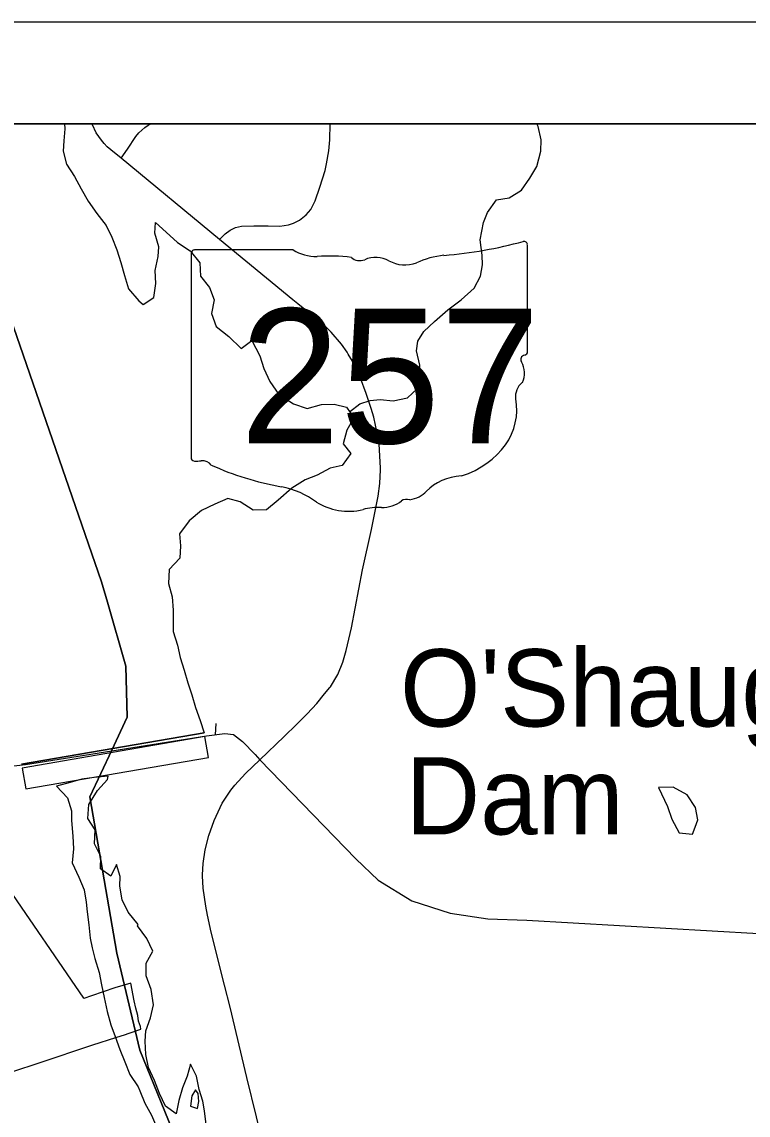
# Model space of a CAD drawing. Extents: x 0 to 34, y 0 to 22.
# Drawn here: x 13.35 to 14.062, y 9.213 to 10.284 of the extents above; entities that cross this region are included whole.
import ezdxf

# ---------------------------------------------------------------- set-up
doc = ezdxf.new("R2010")
doc.units = 0
for name, color, linetype in [('GM_X_Corporation', 7, 'Continuous'), ('GM_X_County_Road', 7, 'Continuous'), ('GM_X_Hydro', 7, 'Continuous'), ('GM_X_Hydro_Text', 7, 'Continuous'), ('GM_X_Major_Lake', 7, 'Continuous'), ('GM_X_Major_River', 7, 'Continuous'), ('GM_X_Minor_Lake', 7, 'Continuous'), ('GM_X_Minor_River', 7, 'Continuous'), ('GM_X_State_Location', 7, 'Continuous'), ('GM_X_State_Route', 7, 'Continuous'), ('GM_X_State_Shield', 7, 'Continuous'), ('GM_X_Township_Road', 7, 'Continuous'), ('SH_Data', 7, 'Continuous')]:
    doc.layers.add(name, color=color, linetype=linetype)

msp = doc.modelspace()

# ---------------------------------------------------------------- linework, layer by layer
at = {"layer": 'GM_X_Corporation'}
for points in [[(19.5646, 10.1841), (12.7646, 10.1841), (12.7646, 8.6719), (12.7953, 8.6676), (12.8119, 8.6756), (12.8296, 8.6783), (12.8448, 8.6761), (12.8988, 8.6726), (13.0467, 8.6615), (13.1161, 8.6564), (13.1948, 8.6507), (13.3525, 8.6386), (13.4613, 8.6292), (13.7169, 8.6042), (13.795, 8.6047), (14.2608, 8.5815), (14.4977, 8.5718), (14.6084, 8.5661), (14.9063, 8.5471), (15.334, 8.5309), (15.3473, 8.5302), (16.0546, 8.4904)], [(13.5392, 9.0957), (13.4655, 9.2762), (13.4429, 9.3712), (13.4167, 9.5246), (13.438, 9.5701), (13.4532, 9.6025), (13.452, 9.6526), (13.4339, 9.7153), (13.4281, 9.7354), (13.3254, 10.0317), (13.2907, 10.1441), (13.2832, 10.1841), (12.7646, 10.1841), (12.7646, 8.6719)], [(17.9872, 10.1841), (13.2832, 10.1841), (13.2907, 10.1441), (13.3254, 10.0317), (13.4281, 9.7354), (13.4339, 9.7153), (13.452, 9.6526), (13.4532, 9.6025), (13.438, 9.5701), (13.4167, 9.5246), (13.4429, 9.3712), (13.4655, 9.2762), (13.5392, 9.0957), (13.554, 9.0226), (13.5893, 8.9175), (13.6099, 8.8643), (13.6779, 8.8077), (13.7002, 8.7685), (13.7209, 8.7116), (13.7246, 8.6669), (13.7169, 8.6042), (13.795, 8.6047), (14.2608, 8.5815)], [(13.3412, 9.2552), (13.3669, 9.2637), (13.4194, 9.2813), (13.4422, 9.2886), (13.4514, 9.2917), (13.454, 9.2926), (13.4664, 9.2968), (13.4662, 9.2993), (13.4644, 9.3045), (13.4635, 9.3102), (13.4617, 9.3173), (13.46, 9.3244), (13.4568, 9.342), (13.4411, 9.3372), (13.4182, 9.3294), (13.4108, 9.3269), (13.4107, 9.327), (13.3332, 9.4401)]]:
    msp.add_lwpolyline(points, dxfattribs=at)
at = {"layer": 'GM_X_County_Road'}
msp.add_lwpolyline([(13.065, 9.5737), (13.1018, 9.5801), (13.1145, 9.5803), (13.1252, 9.5789), (13.1359, 9.5759), (13.213, 9.5505), (13.2403, 9.5469), (13.2511, 9.5459), (13.2722, 9.5464), (13.2818, 9.5474), (13.3193, 9.5524), (13.3535, 9.5562), (13.4382, 9.5696), (13.5308, 9.5842), (13.549, 9.5866), (13.5575, 9.5856), (13.5662, 9.5786), (13.5786, 9.5659), (13.5833, 9.5609)], dxfattribs=at)
at = {"layer": 'GM_X_Hydro'}
for p, q in [((13.5294, 9.5835), (13.3502, 9.5527)), ((13.533, 9.5629), (13.5294, 9.5835)), ((13.3537, 9.5322), (13.533, 9.5629)), ((13.3502, 9.5527), (13.3537, 9.5322))]:
    msp.add_line(p, q, dxfattribs=at)
at = {"layer": 'GM_X_Major_Lake'}
msp.add_line((13.5288, 9.5872), (13.3496, 9.5564), dxfattribs=at)
for points in [[(13.3916, 10.1841), (13.3921, 10.1792), (13.3909, 10.1674), (13.3905, 10.1575), (13.3935, 10.1446), (13.4014, 10.1324), (13.4082, 10.1206), (13.415, 10.1085), (13.4233, 10.0963), (13.4327, 10.0845), (13.438, 10.073), (13.4429, 10.0605), (13.447, 10.0483), (13.4504, 10.0354), (13.4545, 10.0225), (13.4647, 10.0107)], [(13.4647, 10.0107), (13.4687, 10.0072), (13.4794, 10.0139), (13.4811, 10.0275), (13.4806, 10.0405), (13.4834, 10.0541), (13.4843, 10.0636), (13.4804, 10.0769), (13.4809, 10.0875), (13.4914, 10.0779), (13.5026, 10.0678), (13.515, 10.0597), (13.5243, 10.0478), (13.5249, 10.0349), (13.5338, 10.0237), (13.5386, 10.0115), (13.5357, 9.9982), (13.5404, 9.9856), (13.5528, 9.9756), (13.5648, 9.964), (13.5755, 9.9718), (13.5832, 9.9569), (13.5872, 9.9443), (13.5931, 9.9317), (13.602, 9.919), (13.6163, 9.9097), (13.6295, 9.905), (13.6436, 9.9089), (13.6561, 9.9095), (13.6682, 9.9063), (13.6753, 9.8959), (13.6686, 9.8839), (13.665, 9.8706), (13.6725, 9.861), (13.6639, 9.8494), (13.6521, 9.8465), (13.6395, 9.8399), (13.6277, 9.8351), (13.6147, 9.827), (13.6012, 9.8154), (13.5897, 9.8057), (13.5768, 9.8055), (13.564, 9.8137), (13.5519, 9.8169), (13.539, 9.8114), (13.526, 9.8052), (13.5141, 9.7951), (13.5044, 9.7823), (13.5054, 9.7705), (13.5048, 9.7584), (13.4944, 9.7472), (13.4938, 9.7335), (13.4974, 9.7206), (13.4984, 9.7076), (13.4982, 9.6959), (13.4984, 9.6864), (13.5024, 9.673), (13.5052, 9.6612), (13.5092, 9.6486), (13.5128, 9.6364), (13.5165, 9.6246), (13.5201, 9.612), (13.5248, 9.5994), (13.5288, 9.5872)]]:
    msp.add_lwpolyline(points, dxfattribs=at)
at = {"layer": 'GM_X_Major_River'}
msp.add_line((13.3496, 9.5564), (13.5288, 9.5872), dxfattribs=at)
for points in [[(13.3916, 10.1841), (13.3921, 10.1792), (13.3909, 10.1674), (13.3905, 10.1575), (13.3935, 10.1446), (13.4014, 10.1324), (13.4082, 10.1206), (13.415, 10.1085), (13.4233, 10.0963), (13.4327, 10.0845), (13.438, 10.073), (13.4429, 10.0605), (13.447, 10.0483), (13.4504, 10.0354), (13.4545, 10.0225), (13.4647, 10.0107)], [(13.4647, 10.0107), (13.4687, 10.0072), (13.4794, 10.0139), (13.4811, 10.0275), (13.4806, 10.0405), (13.4834, 10.0541), (13.4843, 10.0636), (13.4804, 10.0769), (13.4809, 10.0875), (13.4914, 10.0779), (13.5026, 10.0678), (13.515, 10.0597), (13.5243, 10.0478), (13.5249, 10.0349), (13.5338, 10.0237), (13.5386, 10.0115), (13.5357, 9.9982), (13.5404, 9.9856), (13.5528, 9.9756), (13.5648, 9.964), (13.5755, 9.9718), (13.5832, 9.9569), (13.5872, 9.9443), (13.5931, 9.9317), (13.602, 9.919), (13.6163, 9.9097), (13.6295, 9.905), (13.6436, 9.9089), (13.6561, 9.9095), (13.6682, 9.9063), (13.6753, 9.8959), (13.6686, 9.8839), (13.665, 9.8706), (13.6725, 9.861), (13.6639, 9.8494), (13.6521, 9.8465), (13.6395, 9.8399), (13.6277, 9.8351), (13.6147, 9.827), (13.6012, 9.8154), (13.5897, 9.8057), (13.5768, 9.8055), (13.564, 9.8137), (13.5519, 9.8169), (13.539, 9.8114), (13.526, 9.8052), (13.5141, 9.7951), (13.5044, 9.7823), (13.5054, 9.7705), (13.5048, 9.7584), (13.4944, 9.7472), (13.4938, 9.7335), (13.4974, 9.7206), (13.4984, 9.7076), (13.4982, 9.6959), (13.4984, 9.6864), (13.5024, 9.673), (13.5052, 9.6612), (13.5092, 9.6486), (13.5128, 9.6364), (13.5165, 9.6246), (13.5201, 9.612), (13.5248, 9.5994), (13.5288, 9.5872)], [(13.4346, 9.5447), (13.4209, 9.5436), (13.4088, 9.5417), (13.3973, 9.5384), (13.384, 9.535), (13.3946, 9.5236), (13.3987, 9.5107), (13.3987, 9.5012), (13.3998, 9.486), (13.4005, 9.4735), (13.3993, 9.4598), (13.4057, 9.4457), (13.4109, 9.4335), (13.4128, 9.4214), (13.4139, 9.4119), (13.4154, 9.399), (13.4168, 9.3861), (13.4187, 9.3766), (13.4213, 9.3659), (13.4258, 9.3522), (13.428, 9.3401), (13.4306, 9.3279), (13.4336, 9.3142), (13.437, 9.3009), (13.4415, 9.2895), (13.446, 9.277), (13.4509, 9.2648), (13.4557, 9.2523), (13.464, 9.2401)], [(13.464, 9.3995), (13.4541, 9.4113), (13.4481, 9.4235), (13.4459, 9.4368), (13.4463, 9.4463), (13.4426, 9.4581), (13.4372, 9.4467), (13.427, 9.454), (13.4274, 9.4661), (13.421, 9.4783), (13.4218, 9.492), (13.4147, 9.5034), (13.4155, 9.517), (13.4239, 9.5307), (13.4338, 9.5416), (13.4346, 9.5447)], [(13.5306, 9.2033), (13.5289, 9.2167), (13.5275, 9.2262), (13.5239, 9.2376), (13.5211, 9.2506), (13.5152, 9.2624), (13.512, 9.2507), (13.5073, 9.2394), (13.5037, 9.2269), (13.5012, 9.2137), (13.4907, 9.2214), (13.4848, 9.2337), (13.4801, 9.2466), (13.4742, 9.2593), (13.4713, 9.2718), (13.4708, 9.2851), (13.4713, 9.295), (13.4761, 9.3078), (13.4789, 9.3207), (13.4768, 9.3355), (13.4717, 9.3489), (13.4719, 9.3614), (13.4782, 9.3731), (13.4723, 9.3857), (13.4634, 9.398), (13.464, 9.3995)], [(13.464, 9.2401), (13.4655, 9.2362), (13.4706, 9.2244), (13.4769, 9.2125), (13.4879, 9.1873)], [(13.5201, 9.2373), (13.5166, 9.2313), (13.5153, 9.2214), (13.5221, 9.219)], [(13.5221, 9.219), (13.5234, 9.2259), (13.5227, 9.2338), (13.5201, 9.2373)]]:
    msp.add_lwpolyline(points, dxfattribs=at)
at = {"layer": 'GM_X_Minor_Lake'}
for points in [[(14.0101, 9.4949), (14.0128, 9.5021), (14.0105, 9.5142), (14.0022, 9.5264), (13.9886, 9.5339), (13.9742, 9.5336)], [(13.9742, 9.5336), (13.9829, 9.515), (13.9871, 9.5025), (13.9943, 9.4892), (14.0075, 9.488), (14.0101, 9.4949)]]:
    msp.add_lwpolyline(points, dxfattribs=at)
at = {"layer": 'GM_X_Minor_River'}
for points in [[(13.6712, 9.9018), (13.6814, 9.9097), (13.6913, 9.9131), (13.7011, 9.9139), (13.714, 9.9127), (13.728, 9.9157), (13.7378, 9.9248), (13.7408, 9.9355), (13.7401, 9.9476), (13.737, 9.9616), (13.7382, 9.9711), (13.7442, 9.9806), (13.7544, 9.9905), (13.7677, 10.0019), (13.7805, 10.0117), (13.7934, 10.0231), (13.7995, 10.0349), (13.8017, 10.0459), (13.8013, 10.0553), (13.7994, 10.0705), (13.8025, 10.0876), (13.8066, 10.0974), (13.8153, 10.1096), (13.8278, 10.1115), (13.8399, 10.1191), (13.8479, 10.1308), (13.8547, 10.1422), (13.8588, 10.1574), (13.8592, 10.1684), (13.8562, 10.1817), (13.8547, 10.1841)], [(13.54, 9.5965), (13.5395, 9.5853), (13.5396, 9.585)]]:
    msp.add_lwpolyline(points, dxfattribs=at)
at = {"layer": 'GM_X_State_Route'}
for points in [[(13.6205, 10.0077), (13.6157, 10.0115), (13.5438, 10.0708), (13.4472, 10.1504), (13.437, 10.1587), (13.4337, 10.1616), (13.4307, 10.1648), (13.4279, 10.1681), (13.4229, 10.1754), (13.419, 10.1832), (13.4187, 10.1841)], [(13.644, 9.9891), (13.6342, 9.9966), (13.6205, 10.0077)], [(13.67, 9.9585), (13.6689, 9.9603), (13.6634, 9.9681), (13.6532, 9.9799), (13.6447, 9.9886), (13.644, 9.9891)], [(13.7014, 9.845), (13.7015, 9.847), (13.7003, 9.8701), (13.6967, 9.8889), (13.6951, 9.8966), (13.6925, 9.9053), (13.6876, 9.9197), (13.682, 9.9348), (13.6757, 9.9488), (13.67, 9.9585)], [(13.6525, 9.6324), (13.6597, 9.6445), (13.6645, 9.6565), (13.668, 9.668), (13.6731, 9.6903), (13.6839, 9.7469), (13.6927, 9.7865), (13.6992, 9.8191), (13.7008, 9.8316), (13.7014, 9.845)], [(13.5833, 9.5609), (13.6775, 9.4636), (13.6992, 9.4427), (13.7324, 9.4227), (13.7698, 9.4104), (13.8068, 9.4048), (13.8451, 9.4036), (14.0723, 9.3904), (14.0991, 9.3891), (14.1268, 9.39), (14.1489, 9.3934), (14.1842, 9.4053), (14.2169, 9.4248), (14.2365, 9.4427), (14.2565, 9.4665), (14.2663, 9.484), (14.2791, 9.5138), (14.2854, 9.538), (14.291, 9.5695), (14.3093, 9.6835), (14.3144, 9.7107), (14.3208, 9.7392), (14.3335, 9.7728), (14.3427, 9.7884)], [(13.5833, 9.5609), (13.6071, 9.5837), (13.6191, 9.5953), (13.6295, 9.6057), (13.6392, 9.6159), (13.6468, 9.6253), (13.652, 9.6316), (13.6525, 9.6324)], [(13.5271, 9.4481), (13.5276, 9.4592), (13.5296, 9.4724), (13.5333, 9.4867), (13.5383, 9.5012), (13.5464, 9.5182), (13.5547, 9.5309), (13.5586, 9.5358), (13.5693, 9.5475), (13.5833, 9.5609)], [(13.532, 9.4084), (13.5302, 9.4172), (13.5278, 9.435), (13.5271, 9.4471), (13.5271, 9.4481)], [(13.5485, 9.3399), (13.5354, 9.3918), (13.532, 9.4084)], [(13.7952, 8.6041), (13.7909, 8.6123), (13.7503, 8.704), (13.7279, 8.7713), (13.6989, 8.8523), (13.6706, 8.9337), (13.6563, 8.9771), (13.6306, 9.0465), (13.5895, 9.1723), (13.5705, 9.2494), (13.554, 9.3184), (13.5485, 9.3399)]]:
    msp.add_lwpolyline(points, dxfattribs=at)
at = {"layer": 'GM_X_State_Shield'}
for p, q in [((13.8456, 9.9609), (13.8456, 10.0655)), ((13.516, 10.0571), (13.516, 9.857)), ((13.6158, 10.0606), (13.5192, 10.0606)), ((13.8456, 9.9609), (13.8456, 9.9609))]:
    msp.add_line(p, q, dxfattribs=at)
for centre, major_axis, start_param, end_param in [((13.7282, 10.3334), (0.3495, 0), 4.814394, 5.042369), ((13.8419, 10.066), (0.00367, 0), 6.141152, 7.989035), ((13.5198, 10.0576), (0.00382, 0), 1.712693, 3.28349), ((13.6388, 10.0838), (0.037, 0), 4.042523, 4.731795), ((13.651, 9.9482), (0.133, 0), 1.404758, 1.657858), ((13.6812, 10.0586), (0.0107, 0), 3.836095, 5.185415), ((13.6969, 10.0355), (0.0222, 0), 0.950623, 2.079405), ((13.7728, 9.9995), (0.0703, 0), 1.699011, 2.107814), ((13.7256, 10.0672), (0.0267, 0), 4.081561, 5.145723), ((13.8447, 9.9532), (0.00568, 0), 1.883978, 3.671073), ((13.8417, 9.9605), (0.00393, 0), 5.05454, 6.418171), ((13.8086, 9.9399), (0.0341, 0), 5.934695, 6.695948), ((13.8587, 9.9171), (0.0248, 0), 2.387724, 3.262537), ((13.7478, 9.9037), (0.0874, 0), 5.101752, 6.440018), ((13.5198, 9.8566), (0.00385, 0), 3.00124, 4.508301), ((13.5204, 9.8771), (0.0294, 0), 4.665946, 4.897461), ((13.5264, 9.8455), (0.0106, 0), 0.519207, 1.627899), ((13.6602, 10.0253), (0.2524, 0), 4.195997, 4.488961), ((13.7846, 9.8008), (0.0479, 0), 1.647645, 2.488434), ((13.585, 9.7671), (0.079, 0), 0.823519, 1.323587), ((13.7272, 9.8101), (0.00752, 0), 1.147584, 2.315152), ((13.724, 9.8376), (0.0282, 0), 4.937069, 5.64225), ((13.6704, 9.8445), (0.0501, 0), 4.026481, 4.996735), ((13.6994, 9.7753), (0.0412, 0), 1.495662, 1.94098), ((13.703, 9.8295), (0.0267, 0), 4.691044, 5.507374)]:
    msp.add_ellipse(centre, major_axis=major_axis, ratio=0.8, start_param=start_param, end_param=end_param, dxfattribs=at)
at = {"layer": 'GM_X_Township_Road'}
for points in [[(13.4472, 10.1504), (13.4534, 10.1593), (13.4616, 10.1719), (13.4646, 10.1753), (13.4674, 10.178), (13.4704, 10.1805), (13.4736, 10.1827), (13.4762, 10.1841)], [(13.5438, 10.0708), (13.5492, 10.0763), (13.554, 10.0799), (13.5593, 10.0824), (13.5651, 10.0838), (13.5774, 10.0841), (13.5913, 10.0842), (13.603, 10.084), (13.6114, 10.0851), (13.6162, 10.0867), (13.6222, 10.0897), (13.6288, 10.0949), (13.6332, 10.1001), (13.6376, 10.1087), (13.642, 10.122), (13.6472, 10.1384), (13.6487, 10.1448), (13.651, 10.1576), (13.652, 10.1684), (13.6521, 10.1841)]]:
    msp.add_lwpolyline(points, dxfattribs=at)
at = {"layer": 'SH_Data'}
for p, q in [((12.6646, 10.2841), (19.6646, 10.2841)), ((12.7646, 10.1841), (19.5646, 10.1841))]:
    msp.add_line(p, q, dxfattribs=at)

# ---------------------------------------------------------------- texts
at = {"layer": 'GM_X_Hydro_Text'}
for s, height, rotation, p in [("O'Shaughnessy", 0.075758, 0.0053, (13.7207, 9.5934)), ('Dam', 0.07576, 0.0058, (13.7261, 9.4876))]:
    msp.add_text(s, height=height, rotation=rotation, dxfattribs=at).set_placement(p)
at = {"layer": 'GM_X_State_Location'}
for s in ['s', 'r']:
    msp.add_text(s, height=0.000189, dxfattribs=at).set_placement((13.6771, 9.9438))
msp.add_text('257', height=0.000189, rotation=0, dxfattribs=at).set_placement((13.6102, 9.93))
at = {"layer": 'GM_X_State_Shield'}
msp.add_text('257', height=0.13184, dxfattribs=at).set_placement((13.5639, 9.8711))

doc.saveas('drawing.dxf')
